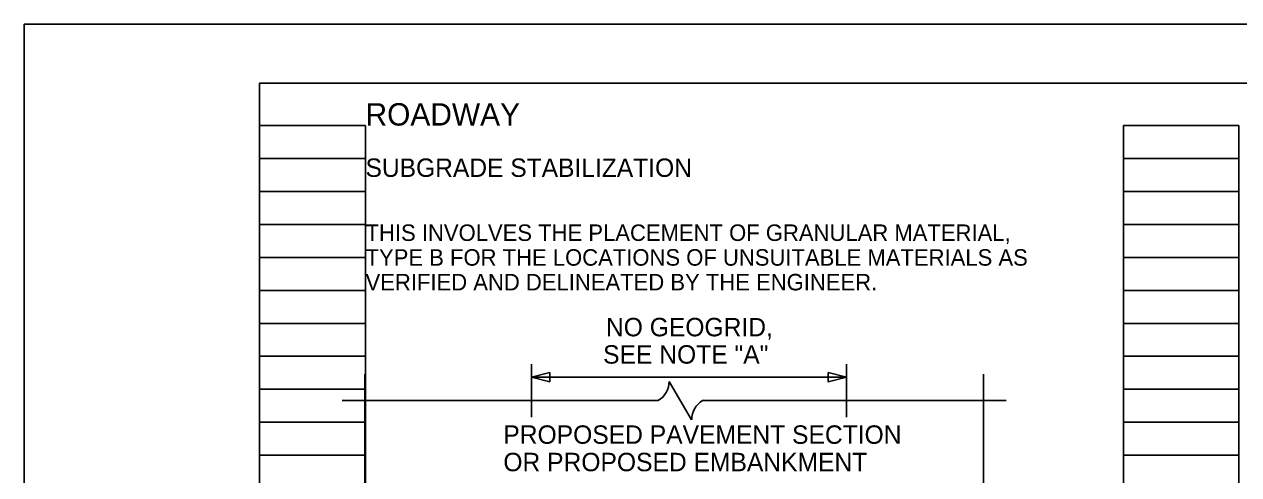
# Model space of a CAD drawing. Extents: x 0 to 34, y 0 to 22.
# Drawn here: x 0 to 10.32, y 18.17 to 22 of the extents above; entities that cross this region are included whole.
import ezdxf

# ---------------------------------------------------------------- set-up
doc = ezdxf.new("R2010")
doc.units = 0
for name, color, linetype in [('Default', 7, 'Continuous'), ('SC_Scratch1', 7, 'Continuous'), ('SH_Border', 7, 'Continuous'), ('SH_Cut_Line', 7, 'Continuous'), ('TX_P_1', 7, 'Continuous'), ('TX_P_Misc', 7, 'Continuous')]:
    doc.layers.add(name, color=color, linetype=linetype)

msp = doc.modelspace()

# ---------------------------------------------------------------- linework, layer by layer
at = {"layer": 'Default'}
for p, q in [((4.31, 19.113), (4.31, 18.664)), ((6.986, 19.113), (6.986, 18.664)), ((2.895, 19.028), (2.895, 16.886)), ((4.31, 19.003), (6.986, 19.003)), ((4.31, 19.003), (4.644, 19.003)), ((6.986, 19.003), (6.952, 19.003)), ((8.151, 19.028), (8.151, 16.886)), ((5.481, 18.966), (5.671, 18.642)), ((2.702, 18.804), (5.388, 18.804)), ((5.764, 18.804), (8.343, 18.804))]:
    msp.add_line(p, q, dxfattribs=at)
for points in [[(4.466, 18.964), (4.31, 19.003), (4.466, 19.042)], [(6.83, 19.042), (6.986, 19.003), (6.83, 18.964)]]:
    msp.add_lwpolyline(points, close=True, dxfattribs=at)
for centre, start, end in [((5.292, 18.966), 300.4422, 360), ((5.86, 18.642), 120.4422, 180)]:
    msp.add_arc(centre, 0.188, start, end, dxfattribs=at)
at = {"layer": 'SC_Scratch1'}
for p, q in [((2, 0.98), (2, 21.14)), ((2, 21.14), (2.9, 21.14)), ((2.9, 0.98), (2.9, 21.14)), ((9.34, 0.98), (9.34, 21.14)), ((9.34, 21.14), (10.32, 21.14)), ((10.32, 0.98), (10.32, 21.14)), ((2, 20.86), (2.9, 20.86)), ((9.34, 20.86), (10.32, 20.86)), ((2, 20.58), (2.9, 20.58)), ((9.34, 20.58), (10.32, 20.58)), ((2, 20.3), (2.9, 20.3)), ((9.34, 20.3), (10.32, 20.3)), ((2, 20.02), (2.9, 20.02)), ((9.34, 20.02), (10.32, 20.02)), ((2, 19.74), (2.9, 19.74)), ((9.34, 19.74), (10.32, 19.74)), ((2, 19.46), (2.9, 19.46)), ((9.34, 19.46), (10.32, 19.46)), ((2, 19.18), (2.9, 19.18)), ((9.34, 19.18), (10.32, 19.18)), ((2, 18.9), (2.9, 18.9)), ((9.34, 18.9), (10.32, 18.9)), ((2, 18.62), (2.9, 18.62)), ((9.34, 18.62), (10.32, 18.62)), ((2, 18.34), (2.9, 18.34)), ((9.34, 18.34), (10.32, 18.34))]:
    msp.add_line(p, q, dxfattribs=at)
at = {"layer": 'SH_Border'}
msp.add_lwpolyline([(2, 21.5), (33.5, 21.5), (33.5, 0.5), (2, 0.5)], close=True, dxfattribs=at)
at = {"layer": 'SH_Cut_Line'}
msp.add_lwpolyline([(0, 0), (34, 0), (34, 22), (0, 22)], close=True, dxfattribs=at)

# ---------------------------------------------------------------- texts
at = {"layer": 'Default'}
for s, p in [('NO GEOGRID, ', (4.943, 19.35)), ('SEE NOTE "A"', (4.919, 19.118)), ('PROPOSED PAVEMENT SECTION', (4.071, 18.437)), ('OR PROPOSED EMBANKMENT', (4.071, 18.204))]:
    msp.add_text(s, height=0.15649, rotation=360, dxfattribs=at).set_placement(p)
at = {"layer": 'TX_P_1'}
for s, height, p in [('ROADWAY', 0.19, (2.9, 21.14)), ('THIS INVOLVES THE PLACEMENT OF GRANULAR MATERIAL, ', 0.14, (2.9, 20.16)), ('TYPE B FOR THE LOCATIONS OF UNSUITABLE MATERIALS AS ', 0.14, (2.9, 19.95)), ('VERIFIED AND DELINEATED BY THE ENGINEER. ', 0.14, (2.9, 19.74))]:
    msp.add_text(s, height=height, dxfattribs=at).set_placement(p)
at = {"layer": 'TX_P_Misc'}
msp.add_text('SUBGRADE STABILIZATION', height=0.15617, dxfattribs=at).set_placement((2.9, 20.704))

doc.saveas('drawing.dxf')
